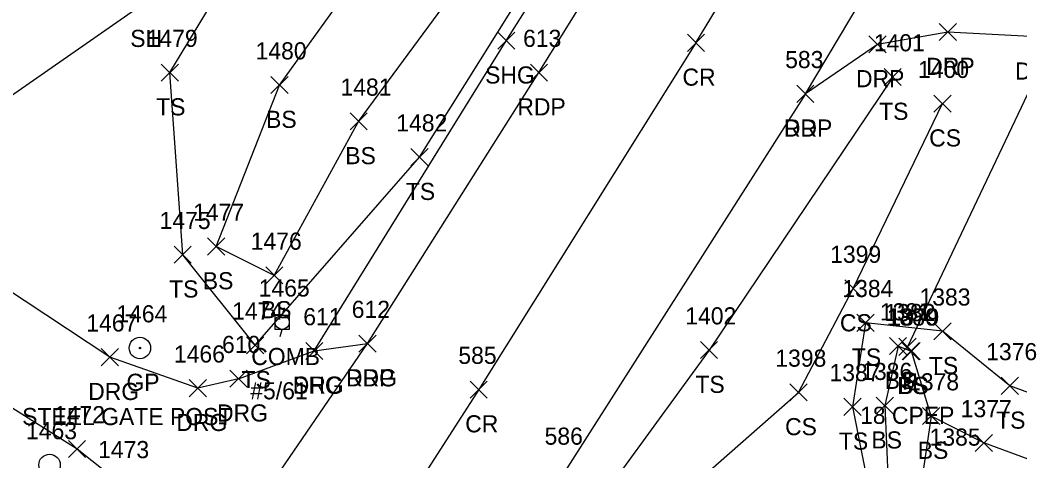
# Model space of a CAD drawing. Extents: x 1639430 to 1640195, y 612006 to 612917.
# Drawn here: x 1639665.7 to 1639782.3, y 612392.7 to 612444.1 of the extents above; entities that cross this region are included whole.
import ezdxf

# ---------------------------------------------------------------- set-up
doc = ezdxf.new("R2010")
doc.units = 0
for name, color, linetype in [('D_A', 7, 'Continuous'), ('D_C', 7, 'Continuous'), ('D_I', 7, 'Continuous'), ('D_TIC', 7, 'Continuous'), ('DCP', 7, 'Continuous'), ('L_A', 7, 'Continuous'), ('L_I', 7, 'Continuous'), ('L_TIC', 7, 'Continuous'), ('LELB', 7, 'Continuous'), ('LSOGP', 7, 'Continuous'), ('P_A', 7, 'Continuous'), ('P_I', 7, 'Continuous'), ('P_TIC', 7, 'Continuous'), ('PET', 7, 'Continuous'), ('PRC', 7, 'Continuous'), ('PSU', 7, 'Continuous'), ('R_A', 7, 'Continuous'), ('R_C', 7, 'Continuous'), ('R_I', 7, 'Continuous'), ('R_TIC', 7, 'Continuous'), ('RDG', 7, 'Continuous'), ('RDP', 7, 'Continuous'), ('RGP', 7, 'Continuous'), ('U_A', 7, 'Continuous'), ('U_C', 7, 'Continuous'), ('U_I', 7, 'Continuous'), ('UP', 7, 'Continuous')]:
    doc.layers.add(name, color=color, linetype=linetype)

msp = doc.modelspace()

# ---------------------------------------------------------------- linework, layer by layer
at = {"layer": 'D_TIC'}
for points in [[(1639768.19, 612404.95), (1639770.19, 612406.95)], [(1639770.19, 612404.95), (1639768.19, 612406.95)]]:
    msp.add_lwpolyline(points, dxfattribs=at)
at = {"layer": 'DCP'}
msp.add_lwpolyline([(1639836.53, 612547.97), (1639769.19, 612405.95)], dxfattribs=at)
at = {"layer": 'L_TIC'}
for points in [[(1639682.14, 612436.98), (1639684.14, 612438.98)], [(1639684.14, 612436.98), (1639682.14, 612438.98)], [(1639766.47, 612436.46), (1639768.47, 612438.46)], [(1639768.47, 612436.46), (1639766.47, 612438.46)], [(1639694.93, 612435.52), (1639696.93, 612437.52)], [(1639696.93, 612435.52), (1639694.93, 612437.52)], [(1639772.28, 612433.35), (1639774.28, 612435.35)], [(1639774.28, 612433.35), (1639772.28, 612435.35)], [(1639704.17, 612431.28), (1639706.17, 612433.28)], [(1639706.17, 612431.28), (1639704.17, 612433.28)], [(1639711.26, 612427.1), (1639713.26, 612429.1)], [(1639713.26, 612427.1), (1639711.26, 612429.1)], [(1639687.55, 612416.67), (1639689.55, 612418.67)], [(1639689.55, 612416.67), (1639687.55, 612418.67)], [(1639683.65, 612415.71), (1639685.65, 612417.71)], [(1639685.65, 612415.71), (1639683.65, 612417.71)], [(1639694.33, 612413.29), (1639696.33, 612415.29)], [(1639696.33, 612413.29), (1639694.33, 612415.29)], [(1639694.33, 612413.29), (1639696.33, 612415.29)], [(1639696.33, 612413.29), (1639694.33, 612415.29)], [(1639761.87, 612411.76), (1639763.87, 612413.76)], [(1639763.87, 612411.76), (1639761.87, 612413.76)], [(1639763.29, 612407.76), (1639765.29, 612409.76)], [(1639765.29, 612407.76), (1639763.29, 612409.76)], [(1639772.28, 612406.77), (1639774.28, 612408.77)], [(1639774.28, 612406.77), (1639772.28, 612408.77)], [(1639692.1, 612405.13), (1639694.1, 612407.13)], [(1639694.1, 612405.13), (1639692.1, 612407.13)], [(1639692.1, 612405.13), (1639694.1, 612407.13)], [(1639694.1, 612405.13), (1639692.1, 612407.13)], [(1639767.09, 612405.04), (1639769.09, 612407.04)], [(1639769.09, 612405.04), (1639767.09, 612407.04)], [(1639745.04, 612404.57), (1639747.04, 612406.57)], [(1639747.04, 612404.57), (1639745.04, 612406.57)], [(1639768.55, 612404.43), (1639770.55, 612406.43)], [(1639770.55, 612404.43), (1639768.55, 612406.43)], [(1639768.65, 612404.44), (1639770.65, 612406.44)], [(1639770.65, 612404.44), (1639768.65, 612406.44)], [(1639780.12, 612400.39), (1639782.12, 612402.39)], [(1639782.12, 612400.39), (1639780.12, 612402.39)], [(1639755.47, 612399.63), (1639757.47, 612401.63)], [(1639757.47, 612399.63), (1639755.47, 612401.63)], [(1639761.78, 612397.94), (1639763.78, 612399.94)], [(1639763.78, 612397.94), (1639761.78, 612399.94)], [(1639765.54, 612398.08), (1639767.54, 612400.08)], [(1639767.54, 612398.08), (1639765.54, 612400.08)], [(1639770.95, 612396.87), (1639772.95, 612398.87)], [(1639772.95, 612396.87), (1639770.95, 612398.87)], [(1639770.95, 612396.87), (1639772.95, 612398.87)], [(1639772.95, 612396.87), (1639770.95, 612398.87)], [(1639777.09, 612393.73), (1639779.09, 612395.73)], [(1639779.09, 612393.73), (1639777.09, 612395.73)]]:
    msp.add_lwpolyline(points, dxfattribs=at)
at = {"layer": 'LELB'}
for points in [[(1639693.1, 612406.13), (1639684.65, 612416.71), (1639683.14, 612437.98), (1639707.71, 612478.57), (1639729.12, 612511.98)], [(1639695.33, 612414.29), (1639688.55, 612417.67), (1639695.93, 612436.52), (1639719.86, 612469.81), (1639740.45, 612503.55)], [(1639695.33, 612414.29), (1639705.17, 612432.28), (1639727.91, 612463.17), (1639746.39, 612499.74)], [(1639693.1, 612406.13), (1639712.26, 612428.1), (1639731.99, 612459.62), (1639753.63, 612498.23)], [(1639767.47, 612437.46), (1639746.04, 612405.57), (1639729.28, 612382.5), (1639739.67, 612371.52), (1639756.35, 612355.43), (1639775.25, 612344.87)], [(1639741.67, 612387.59), (1639756.47, 612400.63), (1639762.87, 612412.76), (1639773.28, 612434.35)], [(1639832.09, 612385.7), (1639802.24, 612393.62), (1639781.12, 612401.39), (1639773.28, 612407.77), (1639764.29, 612408.76), (1639762.78, 612398.94), (1639766.11, 612382.09), (1639764.88, 612355.41)], [(1639826.23, 612376.84), (1639801.72, 612386.01), (1639778.09, 612394.73), (1639771.95, 612397.87), (1639769.65, 612405.44), (1639769.55, 612405.43), (1639768.09, 612406.04), (1639766.54, 612399.08), (1639767.34, 612381.02), (1639767.53, 612353.97)], [(1639771.95, 612397.87), (1639769.47, 612380.94), (1639771.71, 612353.42)]]:
    msp.add_lwpolyline(points, dxfattribs=at)
at = {"layer": 'LSOGP'}
msp.add_lwpolyline([(1639717.74, 612525.52), (1639714.82, 612520.27), (1639697.1, 612487.64), (1639680.04, 612445.97), (1639644.57, 612421.3), (1639635.96, 612403.52), (1639624.25, 612382.3), (1639608.49, 612348.06), (1639600.03, 612336.44), (1639596.7, 612332.58), (1639605.32, 612321.89), (1639618.65, 612314.53), (1639630.7, 612306.67)], dxfattribs=at)
at = {"layer": 'P_TIC'}
for points in [[(1639721.39, 612440.7), (1639723.39, 612442.7)], [(1639723.39, 612440.7), (1639721.39, 612442.7)], [(1639743.51, 612440.45), (1639745.51, 612442.45)], [(1639745.51, 612440.45), (1639743.51, 612442.45)], [(1639725.2, 612436.98), (1639727.2, 612438.98)], [(1639727.2, 612436.98), (1639725.2, 612438.98)], [(1639756.28, 612434.5), (1639758.28, 612436.5)], [(1639758.28, 612434.5), (1639756.28, 612436.5)], [(1639705.2, 612405.33), (1639707.2, 612407.33)], [(1639707.2, 612405.33), (1639705.2, 612407.33)], [(1639698.99, 612404.47), (1639700.99, 612406.47)], [(1639700.99, 612404.47), (1639698.99, 612406.47)], [(1639718.17, 612399.96), (1639720.17, 612401.96)], [(1639720.17, 612399.96), (1639718.17, 612401.96)]]:
    msp.add_lwpolyline(points, dxfattribs=at)
at = {"layer": 'PET'}
for points in [[(1639757.28, 612435.5), (1639791.07, 612492.27)], [(1639571.61, 612204.8), (1639581.27, 612221.94), (1639610.12, 612263.74), (1639636.18, 612301.91), (1639636.72, 612305.17), (1639674.04, 612358.08), (1639681.53, 612370.21), (1639706.2, 612406.33), (1639726.2, 612437.98), (1639749.36, 612475.33)], [(1639757.28, 612435.5), (1639729.28, 612391.52), (1639701.75, 612349.14), (1639688.21, 612328.85), (1639670.81, 612302.33), (1639642.67, 612258.91), (1639622.85, 612231.41), (1639592.08, 612186.98)]]:
    msp.add_lwpolyline(points, dxfattribs=at)
at = {"layer": 'PRC'}
for points in [[(1639744.51, 612441.45), (1639777.38, 612495.69)], [(1639744.51, 612441.45), (1639719.17, 612400.96), (1639690.59, 612356.39), (1639658.59, 612309.05), (1639630.32, 612267.52), (1639611.01, 612239.3), (1639581.06, 612195.34)]]:
    msp.add_lwpolyline(points, dxfattribs=at)
at = {"layer": 'PSU'}
msp.add_lwpolyline([(1639699.99, 612405.47), (1639722.39, 612441.7), (1639745.05, 612477.62), (1639761.99, 612506.29), (1639774.94, 612526.73)], dxfattribs=at)
at = {"layer": 'R_TIC'}
for points in [[(1639772.89, 612441.71), (1639774.89, 612443.71)], [(1639774.89, 612441.71), (1639772.89, 612443.71)], [(1639764.69, 612440.27), (1639766.69, 612442.27)], [(1639766.69, 612440.27), (1639764.69, 612442.27)], [(1639756.28, 612434.5), (1639758.28, 612436.5)], [(1639758.28, 612434.5), (1639756.28, 612436.5)], [(1639705.2, 612405.33), (1639707.2, 612407.33)], [(1639707.2, 612405.33), (1639705.2, 612407.33)], [(1639675.14, 612403.74), (1639677.14, 612405.74)], [(1639677.14, 612403.74), (1639675.14, 612405.74)], [(1639698.99, 612404.47), (1639700.99, 612406.47)], [(1639700.99, 612404.47), (1639698.99, 612406.47)], [(1639690.16, 612401.23), (1639692.16, 612403.23)], [(1639692.16, 612401.23), (1639690.16, 612403.23)], [(1639685.41, 612400.12), (1639687.41, 612402.12)], [(1639687.41, 612400.12), (1639685.41, 612402.12)], [(1639671.32, 612393.03), (1639673.32, 612395.03)], [(1639673.32, 612393.03), (1639671.32, 612395.03)]]:
    msp.add_lwpolyline(points, dxfattribs=at)
at = {"layer": 'RDG'}
for points in [[(1639686.41, 612401.12), (1639676.14, 612404.74), (1639656.23, 612417.91), (1639644.57, 612421.3)], [(1639691.16, 612402.23), (1639699.99, 612405.47), (1639706.2, 612406.33)], [(1639635.96, 612403.52), (1639655.88, 612404.43), (1639672.32, 612394.03), (1639677.47, 612389.95)], [(1639691.16, 612402.23), (1639686.41, 612401.12)]]:
    msp.add_lwpolyline(points, dxfattribs=at)
at = {"layer": 'RDP'}
msp.add_lwpolyline([(1639784.24, 612442.16), (1639773.89, 612442.71), (1639765.69, 612441.27), (1639757.28, 612435.5)], dxfattribs=at)
at = {"layer": 'RGP'}
msp.add_line((1639679.65, 612405.81), (1639679.65, 612405.81), dxfattribs=at)
for centre, radius in [((1639679.65, 612405.81), 1.25), ((1639679.65, 612405.81), 0.0833), ((1639669.11, 612392.16), 1.25)]:
    msp.add_circle(centre, radius, dxfattribs=at)
at = {"layer": 'UP'}
for p, q in [((1639696.5, 612410.49), (1639696.25, 612409.65)), ((1639695.42, 612407.99), (1639695.42, 612409.65)), ((1639695.42, 612409.65), (1639697.08, 612409.65)), ((1639697.08, 612409.65), (1639697.08, 612407.99)), ((1639697.08, 612407.99), (1639695.42, 612407.99)), ((1639696, 612407.15), (1639696.25, 612407.99)), ((1639696.25, 612408.82), (1639696.25, 612408.82))]:
    msp.add_line(p, q, dxfattribs=at)
msp.add_circle((1639696.25, 612408.82), 0.833, dxfattribs=at)

# ---------------------------------------------------------------- texts
at = {"layer": 'D_A'}
msp.add_text('P', height=2, dxfattribs=at).set_placement((1639768.57, 612400.95))
at = {"layer": 'D_C'}
msp.add_text('18 CPEP', height=2, dxfattribs=at).set_placement((1639763.66, 612396.95))
at = {"layer": 'D_I'}
msp.add_text('1382', height=2, dxfattribs=at).set_placement((1639766.5, 612408.95))
at = {"layer": 'L_A'}
for s, p in [('SH', (1639678.53, 612440.97)), ('TS', (1639681.55, 612432.98)), ('TS', (1639765.88, 612432.46)), ('BS', (1639694.37, 612431.52)), ('CS', (1639771.72, 612429.35)), ('BS', (1639703.61, 612427.28)), ('TS', (1639710.67, 612423.1)), ('BS', (1639686.99, 612412.67)), ('TS', (1639683.06, 612411.71)), ('BS', (1639693.77, 612409.29)), ('BS', (1639693.77, 612409.29)), ('CS', (1639761.31, 612407.76)), ('TS', (1639762.7, 612403.76)), ('TS', (1639771.69, 612402.77)), ('TS', (1639691.51, 612401.13)), ('TS', (1639691.51, 612401.13)), ('TS', (1639744.45, 612400.57)), ('BS', (1639766.53, 612401.04)), ('BS', (1639767.99, 612400.43)), ('BS', (1639768.09, 612400.44)), ('CS', (1639754.91, 612395.63)), ('TS', (1639779.53, 612396.39)), ('TS', (1639761.19, 612393.94)), ('BS', (1639764.98, 612394.08)), ('BS', (1639770.39, 612392.87)), ('BS', (1639770.39, 612392.87))]:
    msp.add_text(s, height=2, dxfattribs=at).set_placement(p)
at = {"layer": 'L_I'}
for s, p in [('1479', (1639680.44, 612440.98)), ('1401', (1639765.26, 612440.46)), ('1480', (1639693.15, 612439.52)), ('1400', (1639770.42, 612437.35)), ('1481', (1639703.05, 612435.28)), ('1482', (1639709.56, 612431.1)), ('1477', (1639685.86, 612420.67)), ('1475', (1639681.95, 612419.71)), ('1476', (1639692.58, 612417.29)), ('1476', (1639692.58, 612417.29)), ('1399', (1639760.17, 612415.76)), ('1384', (1639761.59, 612411.76)), ('1383', (1639770.59, 612410.77)), ('1474', (1639690.41, 612409.13)), ('1474', (1639690.41, 612409.13)), ('1402', (1639743.27, 612408.57)), ('1381', (1639765.96, 612409.04)), ('1380', (1639766.77, 612408.43)), ('1379', (1639766.95, 612408.44)), ('1398', (1639753.77, 612403.63)), ('1376', (1639778.37, 612404.39)), ('1387', (1639760.09, 612401.94)), ('1386', (1639763.79, 612402.08)), ('1378', (1639769.26, 612400.87)), ('1378', (1639769.26, 612400.87)), ('1377', (1639775.4, 612397.73)), ('1385', (1639771.77, 612394.41))]:
    msp.add_text(s, height=2, dxfattribs=at).set_placement(p)
at = {"layer": 'P_A'}
for s, p in [('SHG', (1639719.92, 612436.7)), ('CR', (1639742.94, 612436.45)), ('RDP', (1639723.68, 612432.98)), ('RDP', (1639754.77, 612430.5)), ('RDP', (1639703.69, 612401.33)), ('SHG', (1639697.52, 612400.47)), ('CR', (1639717.6, 612395.96))]:
    msp.add_text(s, height=2, dxfattribs=at).set_placement(p)
at = {"layer": 'P_I'}
for s, p in [('613', (1639724.35, 612440.98)), ('583', (1639754.92, 612438.5)), ('611', (1639698.71, 612408.47)), ('612', (1639704.36, 612409.33)), ('585', (1639716.8, 612403.96)), ('586', (1639726.86, 612394.52))]:
    msp.add_text(s, height=2, dxfattribs=at).set_placement(p)
at = {"layer": 'R_A'}
for s, p in [('DRP', (1639771.38, 612437.71)), ('DRP', (1639781.73, 612437.16)), ('DRP', (1639763.18, 612436.27)), ('DRP', (1639754.77, 612430.5)), ('DRG', (1639703.69, 612401.33)), ('GP', (1639678.08, 612400.81)), ('DRG', (1639697.48, 612400.47)), ('DRG', (1639673.62, 612399.74)), ('DRG', (1639688.65, 612397.23)), ('DRG', (1639683.9, 612396.12))]:
    msp.add_text(s, height=2, dxfattribs=at).set_placement(p)
at = {"layer": 'R_C'}
msp.add_text('STEEL GATE POST', height=2, dxfattribs=at).set_placement((1639665.92, 612396.81))
at = {"layer": 'R_I'}
for s, p in [('583', (1639754.92, 612438.5)), ('1464', (1639676.9, 612408.81)), ('611', (1639698.71, 612408.47)), ('612', (1639704.36, 612409.33)), ('1467', (1639673.4, 612407.74)), ('610', (1639689.23, 612405.23)), ('1466', (1639683.62, 612404.12)), ('1472', (1639669.63, 612397.03)), ('1463', (1639666.37, 612395.16)), ('1473', (1639674.78, 612392.95))]:
    msp.add_text(s, height=2, dxfattribs=at).set_placement(p)
at = {"layer": 'U_A'}
msp.add_text('COMB', height=2, dxfattribs=at).set_placement((1639692.64, 612403.82))
at = {"layer": 'U_C'}
msp.add_text('#5/61', height=2, dxfattribs=at).set_placement((1639692.53, 612399.82))
at = {"layer": 'U_I'}
msp.add_text('1465', height=2, dxfattribs=at).set_placement((1639693.51, 612411.82))

doc.saveas('drawing.dxf')
